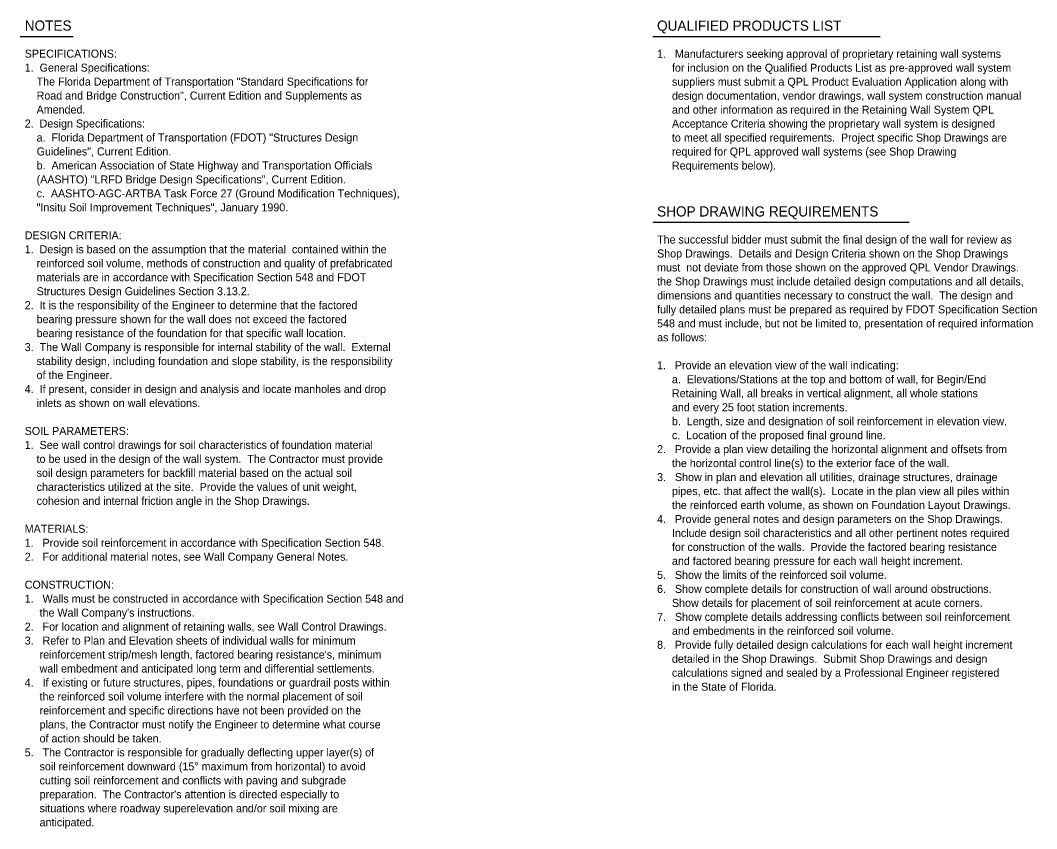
# Model space of a CAD drawing. Extents: x 126777.1 to 126780.68, y 176294.14 to 176295.44.
# Drawn here: x 126777.103 to 126777.903, y 176294.721 to 176295.357 of the extents above; entities that cross this region are included whole.
import ezdxf

# ---------------------------------------------------------------- set-up
doc = ezdxf.new("R2010")
doc.units = 0
doc.layers.add('AdhocPoint_dp', color=7, linetype='Continuous')
doc.layers.add('TextMisc', color=7, linetype='Continuous')

msp = doc.modelspace()

# ---------------------------------------------------------------- linework, layer by layer
at = {"layer": 'AdhocPoint_dp'}
for p, q in [((126777.10321, 176295.34438), (126777.14467, 176295.34438)), ((126777.60078, 176295.34438), (126777.77987, 176295.34438)), ((126777.60078, 176295.19815), (126777.80265, 176295.19815))]:
    msp.add_line(p, q, dxfattribs=at)

# ---------------------------------------------------------------- texts
at = {"layer": 'TextMisc'}
for s, height, p in [('NOTES', 0.008, (126777.10667, 176295.34887)), ('QUALIFIED PRODUCTS LIST', 0.008, (126777.60422, 176295.3488)), ('SPECIFICATIONS:', 0.0063, (126777.10667, 176295.32761)), ('1.   Manufacturers seeking approval of proprietary retaining wall systems', 0.0063, (126777.60422, 176295.32753)), ('1.  General Specifications:', 0.0063, (126777.10667, 176295.31661)), ('     for inclusion on the Qualified Products List as pre-approved wall system', 0.0063, (126777.60422, 176295.31653)), ('    The Florida Department of Transportation "Standard Specifications for', 0.0063, (126777.10667, 176295.30561)), ('     suppliers must submit a QPL Product Evaluation Application along with', 0.0063, (126777.60422, 176295.30553)), ('    Road and Bridge Construction", Current Edition and Supplements as', 0.0063, (126777.10667, 176295.29461)), ('     design documentation, vendor drawings, wall system construction manual', 0.0063, (126777.60422, 176295.29453)), ('    Amended.', 0.0063, (126777.10667, 176295.28361)), ('     and other information as required in the Retaining Wall System QPL ', 0.0063, (126777.60422, 176295.28353)), ('2.  Design Specifications:', 0.0063, (126777.10667, 176295.27261)), ('     Acceptance Criteria showing the proprietary wall system is designed', 0.0063, (126777.60422, 176295.27253)), ('    a.  Florida Department of Transportation (FDOT) "Structures Design', 0.0063, (126777.10667, 176295.26161)), ('     to meet all specified requirements.  Project specific Shop Drawings are', 0.0063, (126777.60422, 176295.26153)), ('    Guidelines", Current Edition.', 0.0063, (126777.10667, 176295.25061)), ('     required for QPL approved wall systems (see Shop Drawing', 0.0063, (126777.60422, 176295.25053)), ('    b.  American Association of State Highway and Transportation Officials', 0.0063, (126777.10667, 176295.23961)), ('     Requirements below).', 0.0063, (126777.60422, 176295.23953)), ('    (AASHTO) "LRFD Bridge Design Specifications", Current Edition.', 0.0063, (126777.10667, 176295.22861)), ('    c.  AASHTO-AGC-ARTBA Task Force 27 (Ground Modification Techniques),', 0.0063, (126777.10667, 176295.21761)), ('    "Insitu Soil Improvement Techniques", January 1990.', 0.0063, (126777.10667, 176295.20661)), ('SHOP DRAWING REQUIREMENTS', 0.008, (126777.60422, 176295.20257)), ('DESIGN CRITERIA:', 0.0063, (126777.10667, 176295.18461)), ('The successful bidder must submit the final design of the wall for review as', 0.0063, (126777.60422, 176295.1813)), ('1.  Design is based on the assumption that the material  contained within the', 0.0063, (126777.10667, 176295.17361)), ('Shop Drawings.  Details and Design Criteria shown on the Shop Drawings', 0.0063, (126777.60422, 176295.1703)), ('    reinforced soil volume, methods of construction and quality of prefabricated', 0.0063, (126777.10667, 176295.16261)), ('must  not deviate from those shown on the approved QPL Vendor Drawings.', 0.0063, (126777.60422, 176295.1593)), ('    materials are in accordance with Specification Section 548 and FDOT ', 0.0063, (126777.10667, 176295.15161)), ('the Shop Drawings must include detailed design computations and all details,', 0.0063, (126777.60422, 176295.1483)), ('    Structures Design Guidelines Section 3.13.2.', 0.0063, (126777.10667, 176295.14061)), ('dimensions and quantities necessary to construct the wall.  The design and', 0.0063, (126777.60422, 176295.1373)), ('2.  It is the responsibility of the Engineer to determine that the factored', 0.0063, (126777.10667, 176295.12961)), ('fully detailed plans must be prepared as required by FDOT Specification Section ', 0.0063, (126777.60422, 176295.1263)), ('    bearing pressure shown for the wall does not exceed the factored', 0.0063, (126777.10667, 176295.11861)), ('548 and must include, but not be limited to, presentation of required information', 0.0063, (126777.60422, 176295.1153)), ('    bearing resistance of the foundation for that specific wall location.', 0.0063, (126777.10667, 176295.10761)), ('as follows:', 0.0063, (126777.60422, 176295.1043)), ('3.  The Wall Company is responsible for internal stability of the wall.  External', 0.0063, (126777.10667, 176295.09661)), ('    stability design, including foundation and slope stability, is the responsibility', 0.0063, (126777.10667, 176295.08561)), ('1.   Provide an elevation view of the wall indicating:', 0.0063, (126777.60422, 176295.0823)), ('    of the Engineer.', 0.0063, (126777.10667, 176295.07461)), ('     a.  Elevations/Stations at the top and bottom of wall, for Begin/End', 0.0063, (126777.60422, 176295.0713)), ('4.  If present, consider in design and analysis and locate manholes and drop', 0.0063, (126777.10667, 176295.06361)), ('     Retaining Wall, all breaks in vertical alignment, all whole stations', 0.0063, (126777.60422, 176295.0603)), ('    inlets as shown on wall elevations.', 0.0063, (126777.10667, 176295.05261)), ('     and every 25 foot station increments.', 0.0063, (126777.60422, 176295.0493)), ('     b.  Length, size and designation of soil reinforcement in elevation view.', 0.0063, (126777.60422, 176295.0383)), ('SOIL PARAMETERS:', 0.0063, (126777.10667, 176295.03061)), ('     c.  Location of the proposed final ground line.', 0.0063, (126777.60422, 176295.0273)), ('1.  See wall control drawings for soil characteristics of foundation material', 0.0063, (126777.10667, 176295.01961)), ('2.   Provide a plan view detailing the horizontal alignment and offsets from', 0.0063, (126777.60422, 176295.0163)), ('    to be used in the design of the wall system.  The Contractor must provide', 0.0063, (126777.10667, 176295.00861)), ('     the horizontal control line(s) to the exterior face of the wall.', 0.0063, (126777.60422, 176295.0053)), ('    soil design parameters for backfill material based on the actual soil', 0.0063, (126777.10667, 176294.99761)), ('3.   Show in plan and elevation all utilities, drainage structures, drainage', 0.0063, (126777.60422, 176294.9943)), ('    characteristics utilized at the site.  Provide the values of unit weight,', 0.0063, (126777.10667, 176294.98661)), ('     pipes, etc. that affect the wall(s).  Locate in the plan view all piles within', 0.0063, (126777.60422, 176294.9833)), ('    cohesion and internal friction angle in the Shop Drawings.', 0.0063, (126777.10667, 176294.97561)), ('     the reinforced earth volume, as shown on Foundation Layout Drawings.', 0.0063, (126777.60422, 176294.9723)), ('4.   Provide general notes and design parameters on the Shop Drawings.', 0.0063, (126777.60422, 176294.9613)), ('MATERIALS:', 0.0063, (126777.10667, 176294.95361)), ('     Include design soil characteristics and all other pertinent notes required', 0.0063, (126777.60422, 176294.9503)), ('1.   Provide soil reinforcement in accordance with Specification Section 548.', 0.0063, (126777.10667, 176294.94261)), ('     for construction of the walls.  Provide the factored bearing resistance', 0.0063, (126777.60422, 176294.9393)), ('2.   For additional material notes, see Wall Company General Notes.', 0.0063, (126777.10667, 176294.93161)), ('     and factored bearing pressure for each wall height increment.', 0.0063, (126777.60422, 176294.9283)), ('5.   Show the limits of the reinforced soil volume.', 0.0063, (126777.60422, 176294.9173)), ('CONSTRUCTION:', 0.0063, (126777.10667, 176294.90961)), ('6.   Show complete details for construction of wall around obstructions.', 0.0063, (126777.60422, 176294.9063)), ('1.   Walls must be constructed in accordance with Specification Section 548 and', 0.0063, (126777.10667, 176294.89861)), ('     Show details for placement of soil reinforcement at acute corners.', 0.0063, (126777.60422, 176294.8953)), ("     the Wall Company's instructions.", 0.0063, (126777.10667, 176294.88761)), ('7.   Show complete details addressing conflicts between soil reinforcement', 0.0063, (126777.60422, 176294.8843)), ('2.   For location and alignment of retaining walls, see Wall Control Drawings.', 0.0063, (126777.10667, 176294.87661)), ('     and embedments in the reinforced soil volume. ', 0.0063, (126777.60422, 176294.8733)), ('3.   Refer to Plan and Elevation sheets of individual walls for minimum', 0.0063, (126777.10667, 176294.86561)), ('8.   Provide fully detailed design calculations for each wall height increment', 0.0063, (126777.60422, 176294.8623)), ("     reinforcement strip/mesh length, factored bearing resistance's, minimum", 0.0063, (126777.10667, 176294.85461)), ('     detailed in the Shop Drawings.  Submit Shop Drawings and design', 0.0063, (126777.60422, 176294.8513)), ('     wall embedment and anticipated long term and differential settlements.', 0.0063, (126777.10667, 176294.84361)), ('     calculations signed and sealed by a Professional Engineer registered', 0.0063, (126777.60422, 176294.8403)), ('4.   If existing or future structures, pipes, foundations or guardrail posts within', 0.0063, (126777.10667, 176294.83261)), ('     in the State of Florida.', 0.0063, (126777.60422, 176294.8293)), ('     the reinforced soil volume interfere with the normal placement of soil', 0.0063, (126777.10667, 176294.82161)), ('     reinforcement and specific directions have not been provided on the', 0.0063, (126777.10667, 176294.81061)), ('     plans, the Contractor must notify the Engineer to determine what course', 0.0063, (126777.10667, 176294.79961)), ('     of action should be taken.', 0.0063, (126777.10667, 176294.78861)), ('5.   The Contractor is responsible for gradually deflecting upper layer(s) of', 0.0063, (126777.10667, 176294.77761)), ('     soil reinforcement downward (15° maximum from horizontal) to avoid', 0.0063, (126777.10667, 176294.76661)), ('     cutting soil reinforcement and conflicts with paving and subgrade', 0.0063, (126777.10667, 176294.75561)), ("     preparation.  The Contractor's attention is directed especially to", 0.0063, (126777.10667, 176294.74461)), ('     situations where roadway superelevation and/or soil mixing are', 0.0063, (126777.10667, 176294.73361)), ('     anticipated.', 0.0063, (126777.10667, 176294.72261))]:
    msp.add_text(s, height=height, dxfattribs=at).set_placement(p)

doc.saveas('drawing.dxf')
